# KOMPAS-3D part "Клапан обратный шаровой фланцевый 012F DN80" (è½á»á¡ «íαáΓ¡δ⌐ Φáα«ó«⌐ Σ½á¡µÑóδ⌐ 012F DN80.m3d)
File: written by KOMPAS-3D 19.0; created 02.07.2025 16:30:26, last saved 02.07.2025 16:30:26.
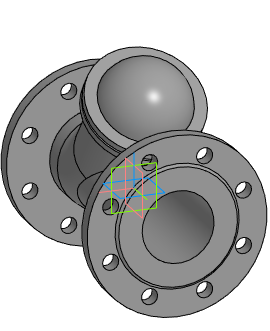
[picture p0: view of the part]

Document properties: Полное имя файла: E:\Dendor Работа Сачек\3D для проектировщиков\5.3 Тип 012F, 012F.Z Клапан обратный шаровой фланцевый\stp_Клапан обратный шаровой фланцевый 012F\Клапан обратный шаровой фланцевый 012F DN80.m3d

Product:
- Part/product: Клапан обратный шаровой фланцевый 012F DN80

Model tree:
1. Операция без истории:1  (labels: Клапан обратный шаровой фланцевый 012F DN80)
